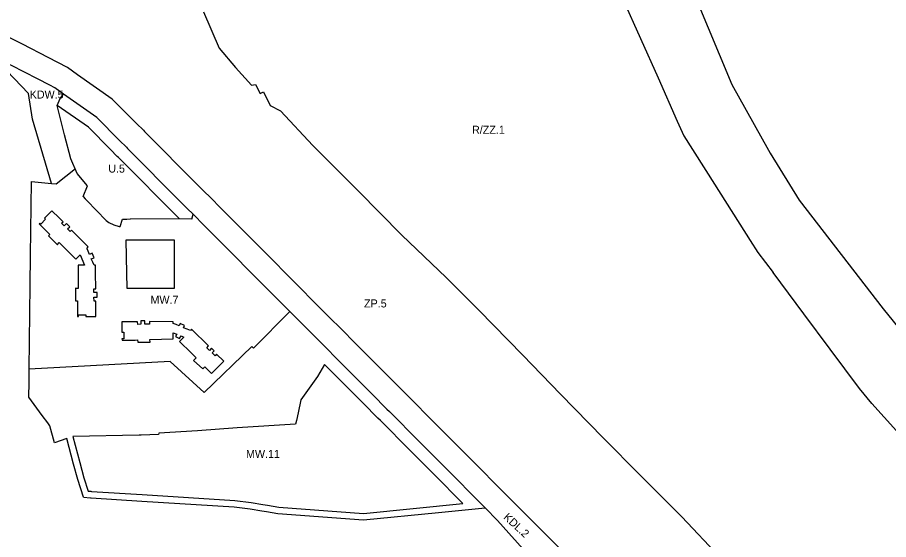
# Model space of a CAD drawing. Extents: x 7427074 to 7428708, y 5545888 to 5547145.
# Drawn here: x 7427887 to 7428431, y 5546303 to 5546629 of the extents above; entities that cross this region are included whole.
import ezdxf

# ---------------------------------------------------------------- set-up
doc = ezdxf.new("R2010")
doc.units = 0
for name, color, linetype in [('linie_rozgraniczajace', 7, 'Continuous'), ('linie_zabudowy_nieprzekraczalne', 7, 'Continuous'), ('linie_zabudowy_obowiazujace', 7, 'Continuous'), ('oznaczenia_przeznaczen', 7, 'Continuous')]:
    doc.layers.add(name, color=color, linetype=linetype)

msp = doc.modelspace()

# ---------------------------------------------------------------- linework, layer by layer
at = {"layer": 'linie_rozgraniczajace'}
for p, q in [((7428310.38, 5546642.61), (7428333.49, 5546587.31)), ((7427896.57, 5546565.65), (7427894.13, 5546581.67)), ((7427908.43, 5546525.57), (7427896.57, 5546565.65)), ((7427942.7, 5546502.44), (7427930.64, 5546514.77)), ((7428375.61, 5546514.96), (7428428.05, 5546447.24)), ((7427996.19, 5546503.29), (7427996.92, 5546506.27)), ((7428428.05, 5546447.24), (7428462.14, 5546404.79)), ((7428198.69, 5546324.88), (7428234.46, 5546289.38))]:
    msp.add_line(p, q, dxfattribs=at)
for points in [[(7428265.39, 5546640.77), (7428287.52, 5546591.46), (7428299.4, 5546564.31), (7428303.6, 5546555.15), (7428322.69, 5546525.14), (7428344.96, 5546489.92), (7428349.78, 5546482.45), (7428359.41, 5546469.8)], [(7428003.56, 5546632.6), (7428013.35, 5546609.96), (7428023.42, 5546597.96), (7428033.51, 5546586.84), (7428035.92, 5546587.2), (7428038.77, 5546581.75), (7428040.88, 5546582.75), (7428045.21, 5546574.1), (7428051.54, 5546570.91), (7428071.82, 5546549.19), (7428100, 5546520.83), (7428127.37, 5546493.12), (7428155.12, 5546466.86), (7428175.47, 5546446.35), (7428202.88, 5546418.24), (7428226.46, 5546394.02), (7428253.17, 5546366.75), (7428276.17, 5546343.39), (7428302.21, 5546317.24), (7428326.22, 5546291.96)], [(7427946.45, 5546578.21), (7427924.84, 5546593.37), (7427918.6, 5546597.94), (7427906.55, 5546604.1), (7427890.37, 5546612.47), (7427886.58, 5546614.33), (7427878.85, 5546618.23)], [(7427822.91, 5546615.31), (7427842.03, 5546611.49), (7427871.42, 5546605.18), (7427894.13, 5546581.67)], [(7427936.76, 5546566.69), (7427916.1, 5546581.17), (7427910.7, 5546585.13), (7427907.42, 5546586.81), (7427899.69, 5546590.77), (7427883.62, 5546599.07), (7427879.89, 5546600.9), (7427875.47, 5546603.13), (7427871.42, 5546605.18)], [(7428333.49, 5546587.31), (7428356.32, 5546546.38), (7428357.4, 5546544.44), (7428375.61, 5546514.96)], [(7427912.01, 5546574.19), (7427913.9, 5546578.55), (7427916.1, 5546581.17)], [(7427946.45, 5546578.21), (7427961.61, 5546562.99), (7427965.91, 5546558.67), (7427966.6, 5546557.98), (7427999.95, 5546524.48), (7428003.94, 5546520.48), (7428007.55, 5546516.86)], [(7427928.28, 5546517.26), (7427931.05, 5546523.94), (7427924.59, 5546531.76), (7427920.59, 5546540.84), (7427916.62, 5546555.89), (7427912.01, 5546574.19)], [(7427936.76, 5546566.69), (7427950.98, 5546552.41), (7427955.29, 5546548.08), (7427955.98, 5546547.39), (7427989.32, 5546513.9), (7427993.31, 5546509.89), (7427996.92, 5546506.27)], [(7427908.43, 5546525.57), (7427911.44, 5546525.28), (7427923.58, 5546534.8)], [(7427894.41, 5546391.96), (7427894.53, 5546401.42), (7427894.56, 5546403.92), (7427894.63, 5546409.55), (7427895.28, 5546461.91), (7427895.51, 5546480.61), (7427896.08, 5546526.75), (7427908.43, 5546525.57)], [(7427928.28, 5546517.26), (7427929.5, 5546515.95), (7427930.64, 5546514.77)], [(7428007.55, 5546516.86), (7428014.56, 5546509.82), (7428030.05, 5546494.27), (7428030.68, 5546493.64), (7428045.44, 5546478.82), (7428056.57, 5546467.65), (7428079.31, 5546444.8), (7428092.33, 5546431.74), (7428095.51, 5546428.55), (7428107.06, 5546416.94), (7428119.51, 5546404.44), (7428128.72, 5546395.2), (7428130.26, 5546393.64), (7428130.65, 5546393.26), (7428148.39, 5546375.45), (7428163.59, 5546360.19), (7428198.69, 5546324.88)], [(7427942.7, 5546502.44), (7427944.33, 5546501.09), (7427947.43, 5546499.58), (7427950.73, 5546498.65), (7427951.5, 5546498.68), (7427952.79, 5546503.1), (7427955.51, 5546503.23), (7427957.86, 5546503.41)], [(7427996.19, 5546503.29), (7427957.86, 5546503.41)], [(7427996.92, 5546506.27), (7428003.93, 5546499.23), (7428019.43, 5546483.67), (7428020.06, 5546483.04), (7428034.81, 5546468.23), (7428045.94, 5546457.06), (7428057.37, 5546445.58), (7428068.68, 5546434.22), (7428081.7, 5546421.15), (7428084.88, 5546417.96), (7428096.43, 5546406.36), (7428108.88, 5546393.86), (7428118.08, 5546384.62), (7428119.64, 5546383.05), (7428120.03, 5546382.66), (7428137.76, 5546364.86), (7428152.96, 5546349.61), (7428179.44, 5546322.97)], [(7428663.59, 5546156.52), (7428643.98, 5546172.6), (7428614.02, 5546197.59), (7428581.43, 5546228.28), (7428557.08, 5546250.81), (7428529.97, 5546275.31), (7428491.74, 5546310.15), (7428487.93, 5546313.58), (7428459.48, 5546345.33), (7428420.98, 5546388.04), (7428413.33, 5546397.53), (7428394.99, 5546422.01), (7428378.49, 5546444.15), (7428359.41, 5546469.8)], [(7428057.37, 5546445.58), (7428034.63, 5546422.56), (7428033.6, 5546423.69), (7428003.96, 5546395.01), (7427982.67, 5546414.4), (7427894.63, 5546409.55)], [(7427928.55, 5546329.56), (7427924.89, 5546340.6), (7427922.36, 5546350.16), (7427918.09, 5546366.24), (7427910.42, 5546363.51), (7427907.56, 5546374.1), (7427906.15, 5546376.02), (7427902.77, 5546380.61), (7427894.41, 5546391.96)], [(7427928.55, 5546329.56), (7427932.81, 5546329.29), (7427933.26, 5546329.26), (7427964.91, 5546327.22), (7428022.62, 5546323.51), (7428032.66, 5546322.29), (7428039.99, 5546321.18)], [(7428103.45, 5546315.44), (7428150.35, 5546320.09), (7428179.44, 5546322.97)], [(7428179.44, 5546322.97), (7428187.14, 5546315.01), (7428226.3, 5546271.29), (7428228.55, 5546266.02), (7428229.25, 5546260.53), (7428229.38, 5546258.91), (7428227.82, 5546247.76)], [(7428039.99, 5546321.18), (7428042.86, 5546320.76), (7428049.98, 5546319.4)], [(7428049.98, 5546319.4), (7428103.45, 5546315.44)]]:
    msp.add_lwpolyline(points, dxfattribs=at)
at = {"layer": 'linie_zabudowy_nieprzekraczalne'}
for p, q in [((7427985.29, 5546490.16), (7427954.94, 5546490.06)), ((7427954.94, 5546490.06), (7427955.37, 5546469.38)), ((7427985.37, 5546460.18), (7427985.29, 5546490.16)), ((7427955.37, 5546469.38), (7427955.56, 5546460.05)), ((7427955.56, 5546460.05), (7427985.37, 5546460.18)), ((7428079.08, 5546412.45), (7428074.64, 5546404.97)), ((7428074.64, 5546404.97), (7428064.34, 5546390.45)), ((7428064.34, 5546390.45), (7428062.6, 5546382.37)), ((7428062.6, 5546382.37), (7428061.54, 5546377.43)), ((7428061.54, 5546377.43), (7428061.02, 5546375.22)), ((7427963.24, 5546368.29), (7427921.87, 5546367.59)), ((7427964.47, 5546368.31), (7427963.24, 5546368.29)), ((7427975.32, 5546368.68), (7427964.47, 5546368.31))]:
    msp.add_line(p, q, dxfattribs=at)
for points in [[(7427931.59, 5546560.54), (7427912.03, 5546574.25)], [(7427988.57, 5546503.32), (7427950.32, 5546541.74), (7427949.63, 5546542.43), (7427945.31, 5546546.76), (7427931.59, 5546560.54)], [(7428165.53, 5546325.61), (7428147.29, 5546343.97), (7428132.09, 5546359.21), (7428114.37, 5546377.01), (7428113.97, 5546377.4), (7428112.41, 5546378.98), (7428103.21, 5546388.21), (7428090.76, 5546400.71), (7428079.08, 5546412.45)], [(7428061.02, 5546375.22), (7428024.43, 5546372.96), (7427999.74, 5546371.1), (7427975.5, 5546369.59), (7427975.32, 5546368.68)], [(7427921.87, 5546367.59), (7427926.23, 5546351.18), (7427928.73, 5546341.74), (7427931.5, 5546333.38), (7427933.07, 5546333.28), (7427933.52, 5546333.25), (7427965.17, 5546331.21), (7428022.99, 5546327.49), (7428033.2, 5546326.25), (7428040.58, 5546325.14), (7428043.53, 5546324.71), (7428050.5, 5546323.37), (7428103.4, 5546319.46), (7428165.53, 5546325.61)]]:
    msp.add_lwpolyline(points, dxfattribs=at)
at = {"layer": 'linie_zabudowy_obowiazujace'}
msp.add_lwpolyline([(7427923.9, 5546493.44), (7427921.03, 5546496.29), (7427920.28, 5546495.53), (7427918.62, 5546497.17), (7427919.95, 5546498.51), (7427917.91, 5546500.53), (7427916.52, 5546499.12), (7427914.87, 5546500.75), (7427915.74, 5546501.63), (7427913.23, 5546504.11), (7427908.81, 5546508.5), (7427904.3, 5546503.98), (7427904.13, 5546503.81), (7427904.27, 5546503.69), (7427904.82, 5546503.13), (7427901.77, 5546500.11), (7427901.22, 5546500.67), (7427900.83, 5546500.29), (7427904.21, 5546496.87), (7427907.45, 5546493.61), (7427906.63, 5546492.79), (7427912.16, 5546487.28), (7427912.29, 5546487.41), (7427913.41, 5546488.54), (7427919.45, 5546482.5), (7427922.98, 5546478.96), (7427923.66, 5546478.29), (7427926.46, 5546481), (7427929.11, 5546474.56), (7427925.21, 5546474.54), (7427925.23, 5546469.81), (7427925.28, 5546460), (7427923.88, 5546460), (7427923.52, 5546460.01), (7427923.47, 5546452.3), (7427923.84, 5546452.28), (7427924.67, 5546452.26), (7427924.7, 5546442.46), (7427925.34, 5546442.46), (7427925.38, 5546443.5), (7427929.9, 5546443.5), (7427929.9, 5546442.47), (7427936.18, 5546442.49), (7427936.19, 5546452.1), (7427935.08, 5546452.09), (7427935.04, 5546454.51), (7427937.09, 5546454.52), (7427937.08, 5546457.39), (7427935.01, 5546457.38), (7427935, 5546459.66), (7427936.14, 5546459.67), (7427936.09, 5546469.66), (7427936.07, 5546474.53), (7427935.09, 5546474.53), (7427934.34, 5546476.4), (7427933.33, 5546478.34), (7427935.15, 5546479.11), (7427933.94, 5546481.95), (7427932.21, 5546481.21), (7427931.38, 5546483.14), (7427930.9, 5546484.71), (7427930.72, 5546485.16), (7427931.46, 5546485.92), (7427923.9, 5546493.44)], dxfattribs=at)
msp.add_lwpolyline([(7427952.56, 5546439.06), (7427952.55, 5546435.87), (7427952.56, 5546432.69), (7427953.72, 5546432.7), (7427953.76, 5546428.52), (7427952.56, 5546428.51), (7427952.57, 5546427.66), (7427960.83, 5546427.74), (7427962.21, 5546427.76), (7427962.37, 5546426.48), (7427970.07, 5546426.5), (7427970.03, 5546428.07), (7427984.63, 5546428.4), (7427984.55, 5546432.25), (7427986.83, 5546431.34), (7427985.91, 5546429.84), (7427988.51, 5546428.78), (7427989.44, 5546430.31), (7427991.21, 5546429.61), (7427988.56, 5546426.89), (7427995.8, 5546419.68), (7427998.83, 5546416.66), (7427997.59, 5546415.33), (7427997.17, 5546414.87), (7428003.03, 5546409.84), (7428004.33, 5546411.07), (7428008.54, 5546406.86), (7428016.11, 5546414.49), (7428011.67, 5546418.8), (7428010.75, 5546417.86), (7428008.86, 5546419.71), (7428010.19, 5546421.08), (7428008.55, 5546422.68), (7428007.16, 5546421.26), (7428005.49, 5546422.9), (7428006.62, 5546424.06), (7427995.96, 5546434.47), (7427995.27, 5546433.68), (7427993.35, 5546434.48), (7427990.99, 5546435.45), (7427991.59, 5546436.89), (7427988.81, 5546438.06), (7427988.21, 5546436.62), (7427986.38, 5546437.39), (7427984.53, 5546438.12), (7427984.46, 5546439.15), (7427969.84, 5546439.2), (7427969.76, 5546437.64), (7427966.9, 5546437.61), (7427966.87, 5546439.65), (7427964.33, 5546439.62), (7427964.35, 5546437.54), (7427962.37, 5546437.52), (7427962.35, 5546439.13), (7427960.37, 5546439.11)], close=True, dxfattribs=at)

# ---------------------------------------------------------------- texts
at = {"layer": 'oznaczenia_przeznaczen'}
for s, p in [('KDW.5', (7427894.92, 5546578.52)), ('R/ZZ.1', (7428171.24, 5546556.52)), ('U.5', (7427944, 5546532.27)), ('MW.7', (7427970.37, 5546450.37)), ('ZP.5', (7428103.78, 5546448.09)), ('MW.11', (7428030.05, 5546354.11))]:
    msp.add_text(s, height=5, dxfattribs=at).set_placement(p)
msp.add_text('KDL.2', height=5, rotation=317.2935, dxfattribs=at).set_placement((7428190.44, 5546316.54))

doc.saveas('drawing.dxf')
